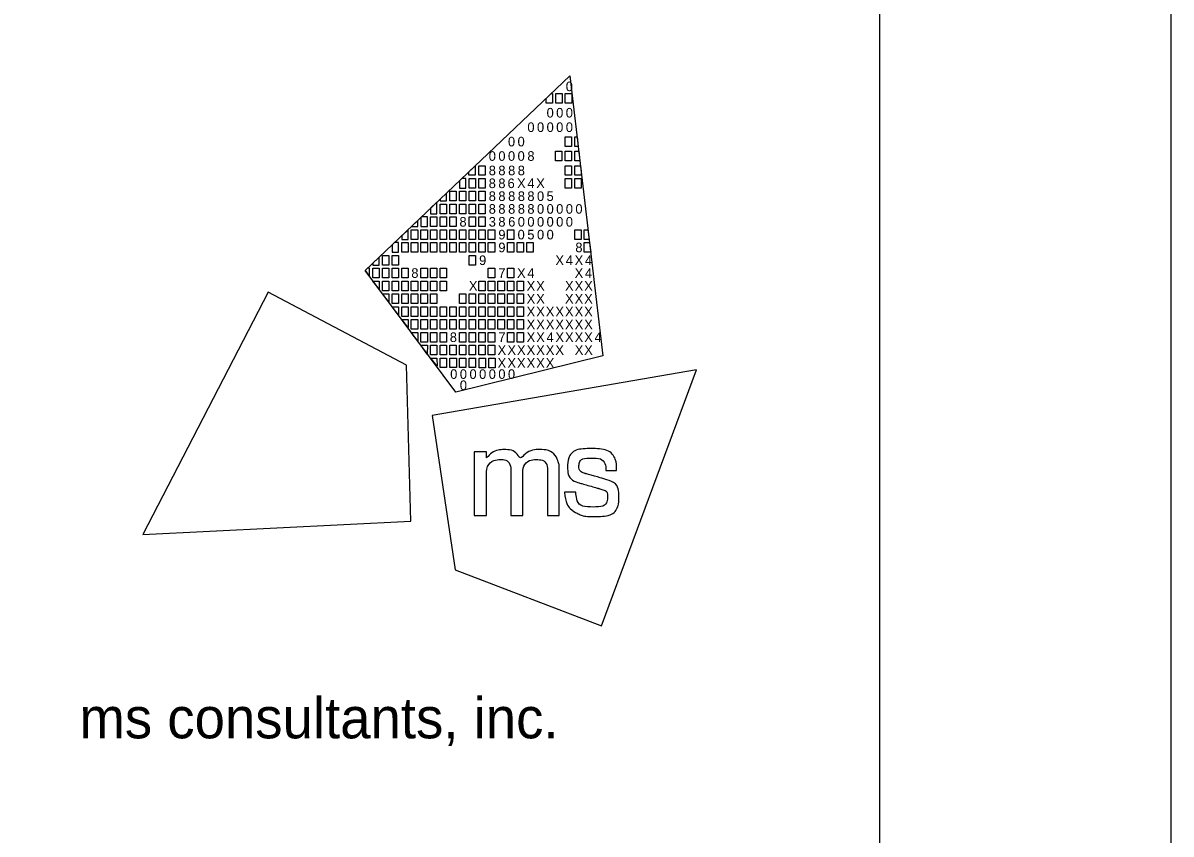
# Model space of a CAD drawing. Extents: x 0 to 34, y 0 to 22.
# Drawn here: x 32.03 to 34, y 2.785 to 4.177 of the extents above; entities that cross this region are included whole.
import ezdxf

# ---------------------------------------------------------------- set-up
doc = ezdxf.new("R2010")
doc.units = 0
for name, color, linetype in [('SH_Border', 7, 'Continuous'), ('SH_Cut_Line', 7, 'Continuous'), ('SH_Data', 7, 'Continuous')]:
    doc.layers.add(name, color=color, linetype=linetype)

msp = doc.modelspace()

# ---------------------------------------------------------------- linework, layer by layer
at = {"layer": 'SH_Border'}
for p, q in [((32.6175, 3.7519), (32.9688, 4.0861)), ((32.9688, 4.0861), (32.9688, 4.0861)), ((32.9688, 4.0861), (33.0253, 3.6052)), ((32.773, 3.543), (32.6175, 3.7519)), ((33.0253, 3.6052), (32.773, 3.543))]:
    msp.add_line(p, q, dxfattribs=at)
for points in [[(1.5, 21.5), (33.5, 21.5), (33.5, 0.5), (1.5, 0.5)], [(32.9279, 4.0472), (32.9369, 4.0558), (32.9389, 4.0558), (32.9389, 4.0393), (32.9279, 4.0393)], [(32.9444, 4.0558), (32.9554, 4.0558), (32.9554, 4.0393), (32.9444, 4.0393)], [(32.9609, 4.0558), (32.9719, 4.0558), (32.9719, 4.0393), (32.9609, 4.0393)], [(32.9606, 3.9815), (32.9716, 3.9815), (32.9716, 3.965), (32.9606, 3.965)], [(32.9771, 3.9815), (32.9811, 3.9815), (32.983, 3.965), (32.9771, 3.965)], [(32.9441, 3.9567), (32.9551, 3.9567), (32.9551, 3.9402), (32.9441, 3.9402)], [(32.9606, 3.9567), (32.9716, 3.9567), (32.9716, 3.9402), (32.9606, 3.9402)], [(32.9771, 3.9567), (32.984, 3.9567), (32.9859, 3.9402), (32.9771, 3.9402)], [(32.7953, 3.9211), (32.8064, 3.9316), (32.8064, 3.9154), (32.7953, 3.9154)], [(32.8123, 3.9319), (32.8233, 3.9319), (32.8233, 3.9154), (32.8123, 3.9154)], [(32.9606, 3.9319), (32.9716, 3.9319), (32.9716, 3.9154), (32.9606, 3.9154)], [(32.9771, 3.9319), (32.9869, 3.9319), (32.9881, 3.9218), (32.9881, 3.9154), (32.9771, 3.9154)], [(32.7958, 3.9099), (32.8068, 3.9099), (32.8068, 3.8934), (32.7958, 3.8934)], [(32.8123, 3.9099), (32.8233, 3.9099), (32.8233, 3.8934), (32.8123, 3.8934)], [(32.9606, 3.9099), (32.9716, 3.9099), (32.9716, 3.8934), (32.9606, 3.8934)], [(32.9771, 3.9099), (32.9881, 3.9099), (32.9881, 3.8934), (32.9771, 3.8934)], [(32.7627, 3.8879), (32.7737, 3.8879), (32.7737, 3.8714), (32.7627, 3.8714)], [(32.7793, 3.8879), (32.7903, 3.8879), (32.7903, 3.8714), (32.7793, 3.8714)], [(32.7958, 3.8879), (32.8068, 3.8879), (32.8068, 3.8714), (32.7958, 3.8714)], [(32.8123, 3.8879), (32.8233, 3.8879), (32.8233, 3.8714), (32.8123, 3.8714)], [(32.7462, 3.8659), (32.7572, 3.8659), (32.7572, 3.8494), (32.7462, 3.8494)], [(32.7627, 3.8659), (32.7737, 3.8659), (32.7737, 3.8494), (32.7627, 3.8494)], [(32.7793, 3.8659), (32.7903, 3.8659), (32.7903, 3.8494), (32.7793, 3.8494)], [(32.7958, 3.8659), (32.8068, 3.8659), (32.8068, 3.8494), (32.7958, 3.8494)], [(32.8123, 3.8659), (32.8233, 3.8659), (32.8233, 3.8494), (32.8123, 3.8494)], [(32.7297, 3.8439), (32.7407, 3.8439), (32.7407, 3.8273), (32.7297, 3.8273)], [(32.7462, 3.8439), (32.7572, 3.8439), (32.7572, 3.8273), (32.7462, 3.8273)], [(32.7627, 3.8439), (32.7737, 3.8439), (32.7737, 3.8273), (32.7627, 3.8273)], [(32.7958, 3.8439), (32.8068, 3.8439), (32.8068, 3.8273), (32.7958, 3.8273)], [(32.8123, 3.8439), (32.8233, 3.8439), (32.8233, 3.8273), (32.8123, 3.8273)], [(32.6967, 3.8218), (32.7077, 3.8218), (32.7077, 3.8053), (32.6967, 3.8053)], [(32.7132, 3.8218), (32.7242, 3.8218), (32.7242, 3.8053), (32.7132, 3.8053)], [(32.7297, 3.8218), (32.7407, 3.8218), (32.7407, 3.8053), (32.7297, 3.8053)], [(32.7462, 3.8218), (32.7572, 3.8218), (32.7572, 3.8053), (32.7462, 3.8053)], [(32.7627, 3.8218), (32.7737, 3.8218), (32.7737, 3.8053), (32.7627, 3.8053)], [(32.7793, 3.8218), (32.7903, 3.8218), (32.7903, 3.8053), (32.7793, 3.8053)], [(32.7958, 3.8218), (32.8068, 3.8218), (32.8068, 3.8053), (32.7958, 3.8053)], [(32.8123, 3.8218), (32.8233, 3.8218), (32.8233, 3.8053), (32.8123, 3.8053)], [(32.8288, 3.8218), (32.8398, 3.8218), (32.8398, 3.8053), (32.8288, 3.8053)], [(32.8618, 3.8218), (32.8728, 3.8218), (32.8728, 3.8053), (32.8618, 3.8053)], [(32.9771, 3.8218), (32.9881, 3.8218), (32.9881, 3.8053), (32.9771, 3.8053)], [(32.9935, 3.8218), (32.9998, 3.8218), (33.0018, 3.8053), (32.9935, 3.8053)], [(32.6802, 3.7998), (32.6912, 3.7998), (32.6912, 3.7833), (32.6802, 3.7833)], [(32.6967, 3.7998), (32.7077, 3.7998), (32.7077, 3.7833), (32.6967, 3.7833)], [(32.7132, 3.7998), (32.7242, 3.7998), (32.7242, 3.7833), (32.7132, 3.7833)], [(32.7297, 3.7998), (32.7407, 3.7998), (32.7407, 3.7833), (32.7297, 3.7833)], [(32.7462, 3.7998), (32.7572, 3.7998), (32.7572, 3.7833), (32.7462, 3.7833)], [(32.7627, 3.7998), (32.7737, 3.7998), (32.7737, 3.7833), (32.7627, 3.7833)], [(32.7793, 3.7998), (32.7903, 3.7998), (32.7903, 3.7833), (32.7793, 3.7833)], [(32.7958, 3.7998), (32.8068, 3.7998), (32.8068, 3.7833), (32.7958, 3.7833)], [(32.8123, 3.7998), (32.8233, 3.7998), (32.8233, 3.7833), (32.8123, 3.7833)], [(32.8288, 3.7998), (32.8398, 3.7998), (32.8398, 3.7833), (32.8288, 3.7833)], [(32.8618, 3.7998), (32.8728, 3.7998), (32.8728, 3.7833), (32.8618, 3.7833)], [(32.8783, 3.7998), (32.8893, 3.7998), (32.8893, 3.7833), (32.8783, 3.7833)], [(32.8947, 3.7998), (32.9057, 3.7998), (32.9057, 3.7833), (32.8947, 3.7833)], [(32.9935, 3.7998), (33.0024, 3.7998), (33.0044, 3.7833), (32.9935, 3.7833)], [(32.6471, 3.7778), (32.6581, 3.7778), (32.6581, 3.7613), (32.6471, 3.7613)], [(32.6637, 3.7778), (32.6747, 3.7778), (32.6747, 3.7613), (32.6637, 3.7613)], [(32.7958, 3.7778), (32.8068, 3.7778), (32.8068, 3.7613), (32.7958, 3.7613)], [(32.6306, 3.7558), (32.6416, 3.7558), (32.6416, 3.7393), (32.6306, 3.7393)], [(32.6471, 3.7558), (32.6581, 3.7558), (32.6581, 3.7393), (32.6471, 3.7393)], [(32.6637, 3.7558), (32.6747, 3.7558), (32.6747, 3.7393), (32.6637, 3.7393)], [(32.6802, 3.7558), (32.6912, 3.7558), (32.6912, 3.7393), (32.6802, 3.7393)], [(32.7132, 3.7558), (32.7242, 3.7558), (32.7242, 3.7393), (32.7132, 3.7393)], [(32.7297, 3.7558), (32.7407, 3.7558), (32.7407, 3.7393), (32.7297, 3.7393)], [(32.7462, 3.7558), (32.7572, 3.7558), (32.7572, 3.7393), (32.7462, 3.7393)], [(32.8288, 3.7558), (32.8398, 3.7558), (32.8398, 3.7393), (32.8288, 3.7393)], [(32.8618, 3.7558), (32.8728, 3.7558), (32.8728, 3.7393), (32.8618, 3.7393)], [(32.6306, 3.7338), (32.6416, 3.7338), (32.6416, 3.72)], [(32.6471, 3.7338), (32.6581, 3.7338), (32.6581, 3.7173), (32.6471, 3.7173)], [(32.6637, 3.7338), (32.6747, 3.7338), (32.6747, 3.7173), (32.6637, 3.7173)], [(32.6802, 3.7338), (32.6912, 3.7338), (32.6912, 3.7173), (32.6802, 3.7173)], [(32.6967, 3.7338), (32.7077, 3.7338), (32.7077, 3.7173), (32.6967, 3.7173)], [(32.7132, 3.7338), (32.7242, 3.7338), (32.7242, 3.7173), (32.7132, 3.7173)], [(32.7297, 3.7338), (32.7407, 3.7338), (32.7407, 3.7173), (32.7297, 3.7173)], [(32.7462, 3.7338), (32.7572, 3.7338), (32.7572, 3.7173), (32.7462, 3.7173)], [(32.8123, 3.7338), (32.8233, 3.7338), (32.8233, 3.7173), (32.8123, 3.7173)], [(32.8288, 3.7338), (32.8398, 3.7338), (32.8398, 3.7173), (32.8288, 3.7173)], [(32.8453, 3.7338), (32.8563, 3.7338), (32.8563, 3.7173), (32.8453, 3.7173)], [(32.8618, 3.7338), (32.8728, 3.7338), (32.8728, 3.7173), (32.8618, 3.7173)], [(32.8783, 3.7338), (32.8893, 3.7338), (32.8893, 3.7173), (32.8783, 3.7173)], [(32.6471, 3.7117), (32.6581, 3.7117), (32.6581, 3.698)], [(32.6637, 3.7117), (32.6747, 3.7117), (32.6747, 3.6952), (32.6637, 3.6952)], [(32.6802, 3.7117), (32.6912, 3.7117), (32.6912, 3.6952), (32.6802, 3.6952)], [(32.6967, 3.7117), (32.7077, 3.7117), (32.7077, 3.6952), (32.6967, 3.6952)], [(32.7132, 3.7117), (32.7242, 3.7117), (32.7242, 3.6952), (32.7132, 3.6952)], [(32.7297, 3.7117), (32.7407, 3.7117), (32.7407, 3.6952), (32.7297, 3.6952)], [(32.7793, 3.7117), (32.7903, 3.7117), (32.7903, 3.6952), (32.7793, 3.6952)], [(32.7958, 3.7117), (32.8068, 3.7117), (32.8068, 3.6952), (32.7958, 3.6952)], [(32.8123, 3.7117), (32.8233, 3.7117), (32.8233, 3.6952), (32.8123, 3.6952)], [(32.8288, 3.7117), (32.8398, 3.7117), (32.8398, 3.6952), (32.8288, 3.6952)], [(32.8453, 3.7117), (32.8563, 3.7117), (32.8563, 3.6952), (32.8453, 3.6952)], [(32.8618, 3.7117), (32.8728, 3.7117), (32.8728, 3.6952), (32.8618, 3.6952)], [(32.8783, 3.7117), (32.8893, 3.7117), (32.8893, 3.6952), (32.8783, 3.6952)], [(32.6637, 3.6897), (32.6747, 3.6897), (32.6747, 3.676)], [(32.6747, 3.6897), (32.6747, 3.6897), (32.6747, 3.6897)], [(32.6802, 3.6897), (32.6912, 3.6897), (32.6912, 3.6732), (32.6802, 3.6732)], [(32.6967, 3.6897), (32.7077, 3.6897), (32.7077, 3.6732), (32.6967, 3.6732)], [(32.7132, 3.6897), (32.7242, 3.6897), (32.7242, 3.6732), (32.7132, 3.6732)], [(32.7297, 3.6897), (32.7407, 3.6897), (32.7407, 3.6732), (32.7297, 3.6732)], [(32.7462, 3.6897), (32.7572, 3.6897), (32.7572, 3.6732), (32.7462, 3.6732)], [(32.7627, 3.6897), (32.7737, 3.6897), (32.7737, 3.6732), (32.7627, 3.6732)], [(32.7793, 3.6897), (32.7903, 3.6897), (32.7903, 3.6732), (32.7793, 3.6732)], [(32.7958, 3.6897), (32.8068, 3.6897), (32.8068, 3.6732), (32.7958, 3.6732)], [(32.8123, 3.6897), (32.8233, 3.6897), (32.8233, 3.6732), (32.8123, 3.6732)], [(32.8288, 3.6897), (32.8398, 3.6897), (32.8398, 3.6732), (32.8288, 3.6732)], [(32.8453, 3.6897), (32.8563, 3.6897), (32.8563, 3.6732), (32.8453, 3.6732)], [(32.8618, 3.6897), (32.8728, 3.6897), (32.8728, 3.6732), (32.8618, 3.6732)], [(32.8783, 3.6897), (32.8893, 3.6897), (32.8893, 3.6732), (32.8783, 3.6732)], [(32.6802, 3.6677), (32.6912, 3.6677), (32.6912, 3.654)], [(32.6967, 3.6677), (32.7077, 3.6677), (32.7077, 3.6512), (32.6967, 3.6512)], [(32.7132, 3.6677), (32.7242, 3.6677), (32.7242, 3.6512), (32.7132, 3.6512)], [(32.7297, 3.6677), (32.7407, 3.6677), (32.7407, 3.6512), (32.7297, 3.6512)], [(32.7462, 3.6677), (32.7572, 3.6677), (32.7572, 3.6512), (32.7462, 3.6512)], [(32.7627, 3.6677), (32.7737, 3.6677), (32.7737, 3.6512), (32.7627, 3.6512)], [(32.7793, 3.6677), (32.7903, 3.6677), (32.7903, 3.6512), (32.7793, 3.6512)], [(32.7958, 3.6677), (32.8068, 3.6677), (32.8068, 3.6512), (32.7958, 3.6512)], [(32.8123, 3.6677), (32.8233, 3.6677), (32.8233, 3.6512), (32.8123, 3.6512)], [(32.8288, 3.6677), (32.8398, 3.6677), (32.8398, 3.6512), (32.8288, 3.6512)], [(32.8453, 3.6677), (32.8563, 3.6677), (32.8563, 3.6512), (32.8453, 3.6512)], [(32.8618, 3.6677), (32.8728, 3.6677), (32.8728, 3.6512), (32.8618, 3.6512)], [(32.8783, 3.6677), (32.8893, 3.6677), (32.8893, 3.6512), (32.8783, 3.6512)], [(32.7077, 3.6305), (32.6965, 3.6457), (32.7077, 3.6457)], [(32.7132, 3.6457), (32.7242, 3.6457), (32.7242, 3.6292), (32.7132, 3.6292)], [(32.7297, 3.6457), (32.7407, 3.6457), (32.7407, 3.6292), (32.7297, 3.6292)], [(32.7462, 3.6457), (32.7572, 3.6457), (32.7572, 3.6292), (32.7462, 3.6292)], [(32.7793, 3.6457), (32.7903, 3.6457), (32.7903, 3.6292), (32.7793, 3.6292)], [(32.7958, 3.6457), (32.8068, 3.6457), (32.8068, 3.6292), (32.7958, 3.6292)], [(32.8123, 3.6457), (32.8233, 3.6457), (32.8233, 3.6292), (32.8123, 3.6292)], [(32.8288, 3.6457), (32.8398, 3.6457), (32.8398, 3.6292), (32.8288, 3.6292)], [(32.8618, 3.6457), (32.8728, 3.6457), (32.8728, 3.6292), (32.8618, 3.6292)], [(32.8783, 3.6457), (32.8893, 3.6457), (32.8893, 3.6292), (32.8783, 3.6292)], [(32.724, 3.6082), (32.7132, 3.6237), (32.7242, 3.6237)], [(32.7297, 3.6237), (32.7407, 3.6237), (32.7407, 3.6072), (32.7297, 3.6072)], [(32.7462, 3.6237), (32.7572, 3.6237), (32.7572, 3.6072), (32.7462, 3.6072)], [(32.7627, 3.6237), (32.7737, 3.6237), (32.7737, 3.6072), (32.7627, 3.6072)], [(32.7793, 3.6237), (32.7903, 3.6237), (32.7903, 3.6072), (32.7793, 3.6072)], [(32.7958, 3.6237), (32.8068, 3.6237), (32.8068, 3.6072), (32.7958, 3.6072)], [(32.8123, 3.6237), (32.8233, 3.6237), (32.8233, 3.6072), (32.8123, 3.6072)], [(32.8288, 3.6237), (32.8398, 3.6237), (32.8398, 3.6072), (32.8288, 3.6072)], [(32.7302, 3.6017), (32.7407, 3.6017), (32.7408, 3.5875)], [(32.7463, 3.6017), (32.7573, 3.6017), (32.7573, 3.5852), (32.7463, 3.5852)], [(32.763, 3.6017), (32.774, 3.6017), (32.774, 3.5852), (32.763, 3.5852)], [(32.7794, 3.6017), (32.7904, 3.6017), (32.7904, 3.5852), (32.7794, 3.5852)], [(32.796, 3.6017), (32.807, 3.6017), (32.807, 3.5852), (32.796, 3.5852)], [(32.8129, 3.6017), (32.8239, 3.6017), (32.8239, 3.5851), (32.8129, 3.5851)], [(32.8296, 3.6017), (32.8406, 3.6017), (32.8406, 3.5851), (32.8296, 3.5851)]]:
    msp.add_lwpolyline(points, close=True, dxfattribs=at)
for points in [[(32.7903, 3.9099), (32.7836, 3.9099), (32.7793, 3.9058), (32.7793, 3.8934), (32.7903, 3.8934), (32.7903, 3.9099)], [(32.7572, 3.8849), (32.7462, 3.8744), (32.7462, 3.8714), (32.7572, 3.8714), (32.7572, 3.8849)], [(32.7407, 3.8691), (32.7297, 3.8587), (32.7297, 3.8494), (32.7407, 3.8494), (32.7407, 3.8691)], [(32.7242, 3.8439), (32.7141, 3.8439), (32.7132, 3.843), (32.7132, 3.8273), (32.7242, 3.8273), (32.7242, 3.8439)], [(32.6912, 3.822), (32.6802, 3.8115), (32.6802, 3.8053), (32.6912, 3.8053), (32.6912, 3.822)], [(32.7077, 3.8377), (32.6968, 3.8273), (32.7077, 3.8273), (32.7077, 3.8377)], [(32.6747, 3.7998), (32.6679, 3.7998), (32.6637, 3.7958), (32.6637, 3.7833), (32.6747, 3.7833), (32.6747, 3.7998)], [(32.6416, 3.7749), (32.6306, 3.7644), (32.6306, 3.7613), (32.6416, 3.7613), (32.6416, 3.7749)], [(32.6251, 3.7558), (32.6216, 3.7558), (32.6175, 3.7519), (32.6251, 3.7417), (32.6251, 3.7558)], [(32.4512, 3.7149), (32.2359, 3.2988), (32.6956, 3.3215), (32.6884, 3.5892), (32.4512, 3.7149)], [(33.0229, 3.1422), (33.1859, 3.5814), (32.7324, 3.5029), (32.7722, 3.2381), (33.0229, 3.1422)]]:
    msp.add_lwpolyline(points, dxfattribs=at)
for points in [[(32.8048, 3.3315), (32.8048, 3.3315), (32.8048, 3.4409), (32.8048, 3.4409), (32.8048, 3.4409), (32.8255, 3.4409), (32.8255, 3.4409), (32.8255, 3.4409), (32.8255, 3.4297), (32.8255, 3.4297), (32.8346, 3.4399), (32.8457, 3.4445), (32.8555, 3.4445), (32.8688, 3.4445), (32.8791, 3.4372), (32.8837, 3.4266), (32.8915, 3.4381), (32.905, 3.4446), (32.9166, 3.4446), (32.9325, 3.4446), (32.9451, 3.435), (32.9494, 3.4213), (32.9494, 3.4212), (32.9494, 3.4212), (32.9494, 3.4212), (32.9501, 3.419), (32.9506, 3.4172), (32.9506, 3.4071), (32.9506, 3.4071), (32.9506, 3.3314), (32.9506, 3.3314), (32.9506, 3.3314), (32.9303, 3.3314), (32.9303, 3.3314), (32.9303, 3.3314), (32.9303, 3.4048), (32.9303, 3.4048), (32.9303, 3.4201), (32.9219, 3.4274), (32.911, 3.4274), (32.8995, 3.4274), (32.8879, 3.4171), (32.8879, 3.4001), (32.8879, 3.4001), (32.8879, 3.3315), (32.8879, 3.3315), (32.8879, 3.3315), (32.8674, 3.3315), (32.8674, 3.3315), (32.8674, 3.3315), (32.8674, 3.4059), (32.8674, 3.4059), (32.8674, 3.4203), (32.8588, 3.4274), (32.8496, 3.4274), (32.8384, 3.4274), (32.8254, 3.417), (32.8254, 3.3962), (32.8254, 3.3962), (32.8254, 3.3315), (32.8254, 3.3315), (32.8254, 3.3315), (32.8048, 3.3315), (32.8048, 3.3315)], [(32.9595, 3.3709), (32.9595, 3.3709), (32.9595, 3.3717), (32.9595, 3.3717), (32.9595, 3.3717), (32.9603, 3.3717), (32.9603, 3.3717), (32.9603, 3.3717), (32.9783, 3.3717), (32.9783, 3.3717), (32.9783, 3.3717), (32.9789, 3.3717), (32.9789, 3.3717), (32.9789, 3.3717), (32.979, 3.371), (32.979, 3.371), (32.9803, 3.3554), (32.9887, 3.346), (33.009, 3.346), (33.0273, 3.346), (33.0333, 3.3554), (33.0333, 3.3631), (33.0333, 3.3732), (33.0256, 3.3758), (33.0175, 3.378), (33.0175, 3.378), (32.987, 3.3867), (32.987, 3.3867), (32.972, 3.3909), (32.9648, 3.4019), (32.9648, 3.4142), (32.9648, 3.4303), (32.9768, 3.4462), (33.0052, 3.4462), (33.0348, 3.4462), (33.0489, 3.4285), (33.0489, 3.4095), (33.0489, 3.4095), (33.0489, 3.4087), (33.0489, 3.4087), (33.0489, 3.4087), (33.0482, 3.4087), (33.0482, 3.4087), (33.0482, 3.4087), (33.0312, 3.4087), (33.0312, 3.4087), (33.0312, 3.4087), (33.0305, 3.4087), (33.0305, 3.4087), (33.0305, 3.4087), (33.0305, 3.4094), (33.0305, 3.4094), (33.0301, 3.4208), (33.0226, 3.43), (33.0056, 3.43), (32.9891, 3.43), (32.9843, 3.4218), (32.9843, 3.4157), (32.9843, 3.4108), (32.9869, 3.4059), (32.9959, 3.4033), (32.9959, 3.4033), (33.0255, 3.3948), (33.0255, 3.3948), (33.0462, 3.3889), (33.0527, 3.3777), (33.0527, 3.3639), (33.0527, 3.3462), (33.041, 3.3298), (33.0087, 3.3298), (32.9952, 3.3298), (32.9877, 3.3321), (32.9823, 3.3348), (32.969, 3.3414), (32.9609, 3.3536), (32.9595, 3.3709)]]:
    msp.add_open_spline(points, degree=3, dxfattribs=at)
at = {"layer": 'SH_Cut_Line'}
msp.add_lwpolyline([(0, 0), (34, 0), (34, 22), (0, 22)], close=True, dxfattribs=at)
at = {"layer": 'SH_Data'}
msp.add_line((32.75, 3.5), (32.75, 3.5), dxfattribs=at)

# ---------------------------------------------------------------- texts
at = {"layer": 'SH_Border'}
for s, height, p in [('0', 0.0165, (32.9617, 4.0597)), ('0', 0.0165, (32.9288, 4.0145)), ('0', 0.0165, (32.9452, 4.0145)), ('0', 0.0165, (32.9617, 4.0145)), ('0', 0.0165, (32.8958, 3.9897)), ('0', 0.0165, (32.9123, 3.9897)), ('0', 0.0165, (32.9288, 3.9897)), ('0', 0.0165, (32.9452, 3.9897)), ('0', 0.0165, (32.9617, 3.9897)), ('0', 0.0165, (32.8625, 3.965)), ('0', 0.0165, (32.879, 3.965)), ('0', 0.0165, (32.8295, 3.9402)), ('0', 0.0165, (32.846, 3.9402)), ('0', 0.0165, (32.8625, 3.9402)), ('0', 0.0165, (32.879, 3.9402)), ('8', 0.0165, (32.8958, 3.9402)), ('8', 0.0165, (32.8295, 3.9154)), ('8', 0.0165, (32.846, 3.9154)), ('8', 0.0165, (32.8628, 3.9154)), ('8', 0.0165, (32.8793, 3.9154)), ('8', 0.0165, (32.8295, 3.8934)), ('8', 0.0165, (32.846, 3.8934)), ('6', 0.0165, (32.8618, 3.8934)), ('X', 0.0165, (32.8781, 3.8934)), ('4', 0.0165, (32.8958, 3.8934)), ('X', 0.0165, (32.911, 3.8934)), ('8', 0.0165, (32.8295, 3.8713)), ('8', 0.0165, (32.846, 3.8713)), ('8', 0.0165, (32.8628, 3.8713)), ('8', 0.0165, (32.8794, 3.8713)), ('8', 0.0165, (32.8958, 3.8713)), ('0', 0.0165, (32.9123, 3.8713)), ('5', 0.0165, (32.9287, 3.8713)), ('8', 0.0165, (32.8295, 3.8494)), ('8', 0.0165, (32.846, 3.8494)), ('8', 0.0165, (32.8628, 3.8494)), ('8', 0.0165, (32.8794, 3.8494)), ('8', 0.0165, (32.8958, 3.8494)), ('0', 0.0165, (32.9123, 3.8494)), ('0', 0.0165, (32.9288, 3.8494)), ('0', 0.0165, (32.9452, 3.8494)), ('0', 0.0165, (32.9617, 3.8494)), ('0', 0.0165, (32.9782, 3.8494)), ('8', 0.0165, (32.7793, 3.8273)), ('3', 0.0165, (32.8295, 3.8273)), ('8', 0.0165, (32.846, 3.8273)), ('6', 0.0165, (32.8629, 3.8273)), ('0', 0.0165, (32.8793, 3.8273)), ('0', 0.0165, (32.8958, 3.8273)), ('0', 0.0165, (32.9123, 3.8273)), ('0', 0.0165, (32.9288, 3.8273)), ('0', 0.0165, (32.9452, 3.8273)), ('0', 0.0165, (32.9617, 3.8273)), ('9', 0.0165, (32.846, 3.8053)), ('0', 0.0165, (32.879, 3.8053)), ('5', 0.0165, (32.8957, 3.8053)), ('0', 0.0165, (32.9123, 3.8053)), ('0', 0.0165, (32.9288, 3.8053)), ('9', 0.0165, (32.846, 3.7833)), ('8', 0.0165, (32.9781, 3.7833)), ('9', 0.0165, (32.813, 3.7613)), ('X', 0.0165, (32.9439, 3.7613)), ('4', 0.0165, (32.9617, 3.7613)), ('X', 0.0165, (32.9769, 3.7613)), ('4', 0.0165, (32.9946, 3.7613)), ('8', 0.0165, (32.6967, 3.7393)), ('7', 0.0165, (32.846, 3.7393)), ('X', 0.0165, (32.8781, 3.7393)), ('4', 0.0165, (32.8958, 3.7393)), ('X', 0.0165, (32.9769, 3.7393)), ('4', 0.0165, (32.9946, 3.7393)), ('X', 0.0165, (32.7955, 3.7173)), ('X', 0.0165, (32.8945, 3.7173)), ('X', 0.0165, (32.911, 3.7173)), ('X', 0.0165, (32.9604, 3.7173)), ('X', 0.0165, (32.9769, 3.7173)), ('X', 0.0165, (32.9933, 3.7173)), ('X', 0.0165, (32.8945, 3.6952)), ('X', 0.0165, (32.911, 3.6952)), ('X', 0.0165, (32.9604, 3.6952)), ('X', 0.0165, (32.9769, 3.6952)), ('X', 0.0165, (32.9933, 3.6952)), ('X', 0.0165, (32.8945, 3.6732)), ('X', 0.0165, (32.911, 3.6732)), ('X', 0.0165, (32.9274, 3.6732)), ('X', 0.0165, (32.9439, 3.6732)), ('X', 0.0165, (32.9604, 3.6732)), ('X', 0.0165, (32.9769, 3.6732)), ('X', 0.0165, (32.9933, 3.6732)), ('X', 0.0165, (32.8945, 3.6512)), ('X', 0.0165, (32.911, 3.6512)), ('X', 0.0165, (32.9274, 3.6512)), ('X', 0.0165, (32.9439, 3.6512)), ('X', 0.0165, (32.9604, 3.6512)), ('X', 0.0165, (32.9769, 3.6512)), ('X', 0.0165, (32.9933, 3.6512)), ('8', 0.0165, (32.7627, 3.6292)), ('7', 0.0165, (32.846, 3.6292)), ('X', 0.0165, (32.8945, 3.6292)), ('X', 0.0165, (32.911, 3.6292)), ('4', 0.0165, (32.9288, 3.6292)), ('X', 0.0165, (32.9439, 3.6292)), ('X', 0.0165, (32.9604, 3.6292)), ('X', 0.0165, (32.9769, 3.6292)), ('X', 0.0165, (32.9933, 3.6292)), ('4', 0.0165, (33.0111, 3.6292)), ('X', 0.0165, (32.8447, 3.6072)), ('X', 0.0165, (32.8616, 3.6072)), ('X', 0.0165, (32.878, 3.6072)), ('X', 0.0165, (32.8945, 3.6072)), ('X', 0.0165, (32.911, 3.6072)), ('X', 0.0165, (32.9274, 3.6072)), ('X', 0.0165, (32.9439, 3.6072)), ('X', 0.0165, (32.9771, 3.6072)), ('X', 0.0165, (32.9933, 3.6072)), ('X', 0.0165, (32.8447, 3.5851)), ('X', 0.0165, (32.8616, 3.5851)), ('X', 0.0165, (32.878, 3.5851)), ('X', 0.0165, (32.8945, 3.5851)), ('X', 0.0165, (32.911, 3.5851)), ('X', 0.0165, (32.9274, 3.5851)), ('0', 0.0165, (32.7634, 3.5659)), ('0', 0.0165, (32.7799, 3.5659)), ('0', 0.0165, (32.7965, 3.5659)), ('0', 0.0165, (32.813, 3.5659)), ('0', 0.0165, (32.8295, 3.5659)), ('0', 0.0165, (32.846, 3.5659)), ('0', 0.0165, (32.8625, 3.5659)), ('0', 0.0165, (32.7799, 3.5467)), ('ms consultants, inc.', 0.07, (32.1273, 2.9489))]:
    msp.add_text(s, height=height, rotation=360, dxfattribs=at).set_placement(p)

doc.saveas('drawing.dxf')
